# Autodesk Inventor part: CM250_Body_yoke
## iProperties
Author: ovrein
Created: 2001-03
Part Number: CM250_Body_yoke
Material: S355J2G3
Document SubType Name: Modeling
Designer: ovrein
Control State: 0
Master: False
Checked Out: False
Last Check In Date: 2001-07-27
PropertySet Name: Design Tracking Control
Last Check In By: ovrein
Shininess: 41.0
PropertySet Name: _Private Model Information
Density: 0.0
Volumn: 0.0
Area: 0.0
PropertySet Name: Model Information
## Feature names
1. Extrusion1
2. rod hole [Extrusion]
3. Extrusion5
4. Revolution1
5. Extrusion7
6. Revolution2
7. Fillet3
8. Extrusion9
9. Revolution3
10. Mirror1
11. Chamfer2
